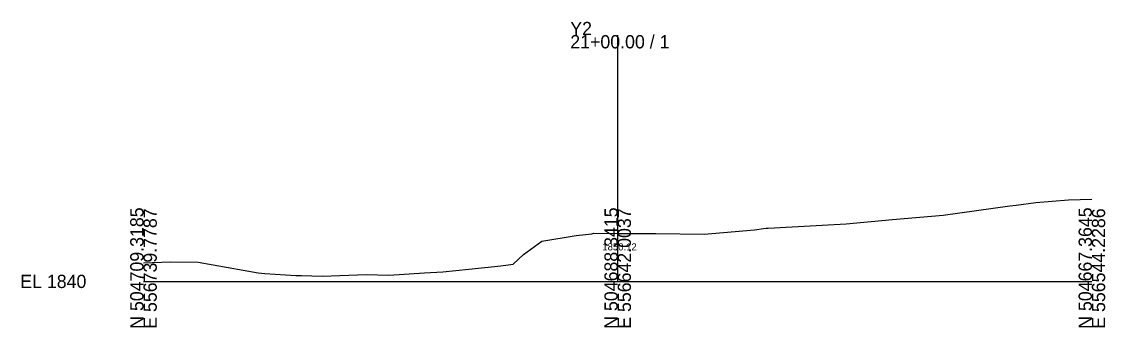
# Model space of a CAD drawing. Extents: x -26 to 1503, y -10 to 3574.
# Drawn here: x -25.7 to 202.8, y 990.3 to 1054.8 of the extents above; entities that cross this region are included whole.
import ezdxf

# ---------------------------------------------------------------- set-up
doc = ezdxf.new("R2010")
doc.units = 0
for name, color, linetype in [('Default', 7, 'Continuous'), ('Exist Cross Section Cell', 7, 'Continuous'), ('Exist XS Center Line Elevation Label', 7, 'Continuous'), ('Exist XS Ground Line', 7, 'Continuous')]:
    doc.layers.add(name, color=color, linetype=linetype)

msp = doc.modelspace()

# ---------------------------------------------------------------- linework, layer by layer
at = {"layer": 'Exist Cross Section Cell'}
for p, q in [((100, 1000), (100, 1051.95)), ((0, 1000), (100, 1000)), ((100, 1000), (200, 1000))]:
    msp.add_line(p, q, dxfattribs=at)
at = {"layer": 'Exist XS Ground Line'}
for p, q in [((188.18, 1016.67), (195.09, 1017.21)), ((195.09, 1017.21), (200, 1017.32)), ((168.67, 1013.97), (182.68, 1015.92)), ((182.68, 1015.92), (184.02, 1016.05)), ((184.02, 1016.05), (188.18, 1016.67)), ((148.18, 1012.11), (157.97, 1013.03)), ((157.97, 1013.03), (168.67, 1013.97)), ((94.54, 1010.04), (94.96, 1010.14)), ((94.96, 1010.14), (100, 1010.12)), ((100, 1010.12), (103.38, 1010.11)), ((103.38, 1010.11), (105.13, 1010.13)), ((105.13, 1010.13), (106.24, 1010.12)), ((106.24, 1010.12), (106.63, 1010.12)), ((106.63, 1010.12), (108.07, 1010.13)), ((108.07, 1010.13), (118.24, 1009.98)), ((118.24, 1009.98), (128.84, 1010.9)), ((128.84, 1010.9), (130.76, 1011.17)), ((130.76, 1011.17), (131.33, 1011.22)), ((131.33, 1011.22), (131.72, 1011.24)), ((131.72, 1011.24), (148.18, 1012.11)), ((80.16, 1005.65), (84.02, 1008.45)), ((84.02, 1008.45), (91.25, 1009.67)), ((91.25, 1009.67), (94.54, 1010.04)), ((77.98, 1003.61), (80.16, 1005.65)), ((0, 1003.94), (5.75, 1004.15)), ((5.75, 1004.15), (11.52, 1004.08)), ((11.52, 1004.08), (24.17, 1001.79)), ((68.6, 1002.57), (75.34, 1003.27)), ((75.34, 1003.27), (77.98, 1003.61)), ((24.17, 1001.79), (25.58, 1001.68)), ((25.58, 1001.68), (32.14, 1001.27)), ((32.14, 1001.27), (33.31, 1001.24)), ((33.31, 1001.24), (37.69, 1001.1)), ((37.69, 1001.1), (47.02, 1001.43)), ((47.02, 1001.43), (51.72, 1001.34)), ((51.72, 1001.34), (59.28, 1001.83)), ((59.28, 1001.83), (63.1, 1002.01)), ((63.1, 1002.01), (68.6, 1002.57))]:
    msp.add_line(p, q, dxfattribs=at)

# ---------------------------------------------------------------- texts
at = {"layer": 'Default'}
msp.add_text('-', height=0.0001, dxfattribs=at).set_placement((0, 1000))
at = {"layer": 'Exist Cross Section Cell'}
for s, p in [('Y2', (90, 1051.95)), ('21+00.00 / 1', (90, 1049.15)), ('EL 1840', (-26, 998.6))]:
    msp.add_text(s, height=2.8, dxfattribs=at).set_placement(p)
for s, p in [('N 504709.3185', (0, 990)), ('E 556739.7787', (2.8, 990)), ('N 504688.3415', (100, 990)), ('E 556642.0037', (102.8, 990)), ('N 504667.3645', (200, 990)), ('E 556544.2286', (202.8, 990))]:
    msp.add_text(s, height=2.8, rotation=90, dxfattribs=at).set_placement(p)
at = {"layer": 'Exist XS Center Line Elevation Label'}
msp.add_text('1850.12', height=1.5, dxfattribs=at).set_placement((96.76, 1006.53))

doc.saveas('drawing.dxf')
